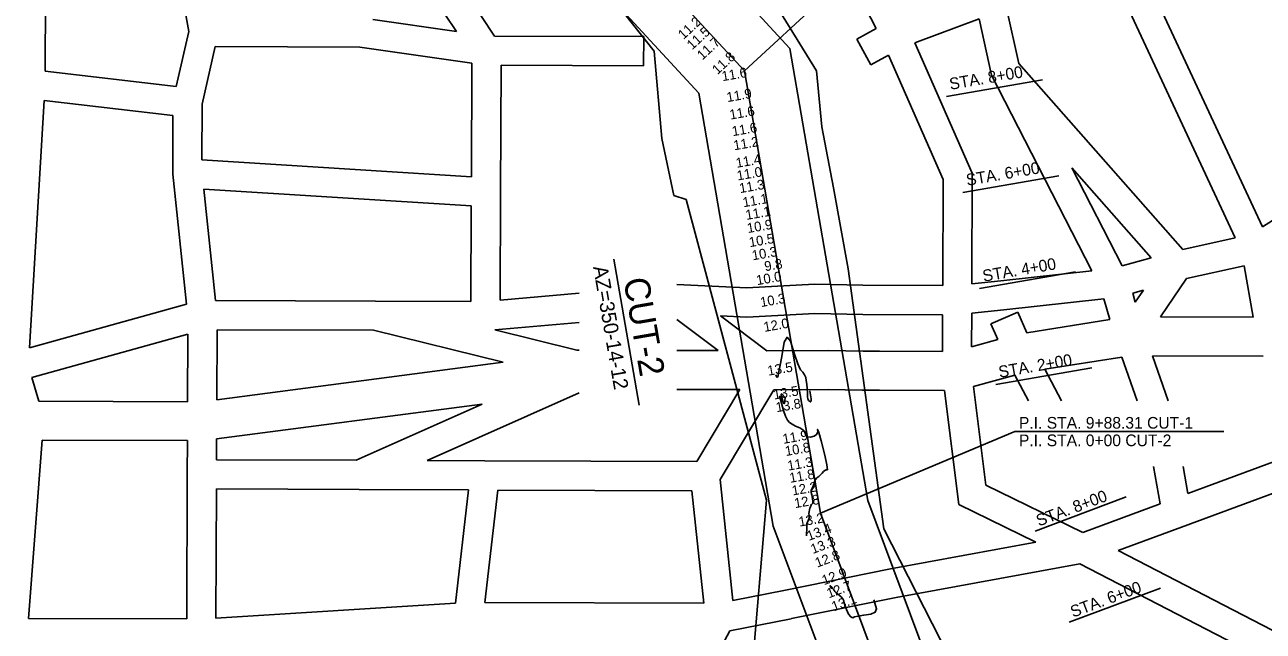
# Model space of a CAD drawing. Extents: x 503330 to 511530, y 1310349 to 1316149.
# Drawn here: x 506410 to 508954, y 1311832 to 1313078 of the extents above; entities that cross this region are included whole.
import ezdxf

# ---------------------------------------------------------------- set-up
doc = ezdxf.new("R2010")
doc.units = 0
for name, color, linetype in [('Level 1', 7, 'Continuous'), ('Level 23', 7, 'Continuous'), ('Level 32', 7, 'Continuous'), ('Level 49', 7, 'Continuous'), ('Level 5', 7, 'Continuous'), ('Level 50', 7, 'Continuous'), ('Level 51', 7, 'Continuous'), ('Level 56', 7, 'Continuous'), ('Level 6', 7, 'Continuous')]:
    doc.layers.add(name, color=color, linetype=linetype)

msp = doc.modelspace()

# ---------------------------------------------------------------- linework, layer by layer
at = {"layer": 'Level 1'}
for points in [[(508022.9, 1312326.1), (508025.1, 1312310.1), (508025.1, 1312305.2), (508024, 1312303.5), (508021.9, 1312305), (508020.2, 1312306.5), (508019.1, 1312308.1), (508018.5, 1312309.7), (508018, 1312314.1), (508017.5, 1312321.2), (508017.1, 1312331), (508016.4, 1312339.6), (508015.4, 1312347.1), (508014.2, 1312353.5), (508011.8, 1312359.3), (508008.3, 1312364.7), (508003.7, 1312369.6), (507998, 1312381.8), (507991.1, 1312401.4), (507983.1, 1312428.2), (507976, 1312436.4), (507969.9, 1312425.9), (507964.8, 1312396.8), (507961, 1312375.5), (507958.5, 1312362.3), (507957.3, 1312356.9), (507956.1, 1312354.2), (507955, 1312354), (507952.8, 1312358.9)], [(508015.7, 1312028.7), (508016.1, 1312046.3), (508016.7, 1312052.9), (508017.7, 1312057.2), (508019.1, 1312059.3), (508020.1, 1312061.3), (508020.7, 1312063.1), (508020.9, 1312064.8), (508021, 1312067.2), (508020.9, 1312070.4), (508020.7, 1312074.3), (508020.9, 1312078), (508021.6, 1312081.6), (508022.7, 1312085), (508023.8, 1312087.7), (508024.7, 1312089.7), (508025.4, 1312091.1), (508026.3, 1312092.5), (508027.4, 1312094.1), (508028.5, 1312095.7), (508028.7, 1312099.2), (508028, 1312104.8), (508026.4, 1312112.4), (508025.4, 1312117.7), (508025.1, 1312120.8), (508025.4, 1312121.6), (508026.1, 1312123.2), (508027.3, 1312125.6), (508028.9, 1312128.9), (508030.3, 1312132.4), (508031.3, 1312136.1), (508032.1, 1312140.2), (508034, 1312143.9), (508036.9, 1312147.4), (508041, 1312150.5), (508044.7, 1312153.7), (508047.9, 1312157), (508050.8, 1312160.4), (508053.5, 1312162.8), (508056.1, 1312164), (508058.7, 1312164.2), (508057.8, 1312174.1), (508053.5, 1312193.8), (508045.8, 1312223.2), (508040.8, 1312240.9), (508038.4, 1312246.8), (508038.7, 1312241.1), (508036.3, 1312236.5), (508031.4, 1312233.1), (508023.8, 1312230.8), (508018.1, 1312231.4), (508014.3, 1312234.8), (508012.4, 1312241.1), (508008.3, 1312246.3), (508002, 1312250.5), (507993.5, 1312253.8), (507986.4, 1312257.4), (507980.8, 1312261.5), (507976.6, 1312266), (507972.5, 1312274), (507968.4, 1312285.6), (507960.2, 1312316)], [(508067.1, 1311919.2), (508064.4, 1311925.5), (508064.6, 1311926.2), (508066.2, 1311924.4), (508069.4, 1311920.3), (508071.7, 1311917.2), (508073.2, 1311915.2), (508073.8, 1311914.3), (508076.2, 1311912.1), (508080.4, 1311908.5), (508086.3, 1311903.5), (508090.3, 1311899), (508092.5, 1311894.7), (508092.8, 1311890.9), (508094.5, 1311885.1), (508097.6, 1311877.3), (508102.2, 1311867.6), (508106.6, 1311861.8), (508110.6, 1311859.8), (508114.5, 1311861.7), (508122, 1311863.6), (508133.2, 1311865.5), (508148, 1311867.4), (508156.9, 1311871.7), (508159.8, 1311878.5), (508153.7, 1311896.9)]]:
    msp.add_lwpolyline(points, dxfattribs=at)
msp.add_lwpolyline([(507971.7, 1312312.8), (507971.8, 1312310.2), (507971.5, 1312307.9), (507971, 1312304.5), (507970.3, 1312300), (507969, 1312300.2), (507967.1, 1312304.9), (507964.6, 1312314.3), (507964, 1312319.3), (507965.3, 1312320)], close=True, dxfattribs=at)
at = {"layer": 'Level 23'}
for p, q in [((508468, 1312445.6), (508639, 1312472.4)), ((508743, 1312478.1), (508933.3, 1312477.4)), ((508354.9, 1312416.9), (508408.5, 1312431.8)), ((507548.6, 1312409.9), (507544.4, 1312409.9)), ((507834.2, 1312408.8), (507749.4, 1312409.1)), ((507934.2, 1312408.4), (508060.9, 1312409.1)), ((508060.9, 1312409.1), (508131.8, 1312407.7)), ((508131.8, 1312407.7), (508166, 1312407.6)), ((508166, 1312407.6), (508294.9, 1312407.1)), ((508505.1, 1312370.4), (508663.5, 1312395.3)), ((508726, 1312398.2), (508953.7, 1312397.4)), ((507393, 1312385.3), (506804.7, 1312308)), ((508358.9, 1312335), (508443.5, 1312358.4)), ((507878.6, 1312328.7), (507749.4, 1312329.1)), ((507948.4, 1312328.5), (508060.3, 1312329.1)), ((508060.3, 1312329.1), (508130.2, 1312327.7)), ((508130.2, 1312327.7), (508165.7, 1312327.6)), ((508165.7, 1312327.6), (508299.4, 1312327.1)), ((506744.7, 1312303.9), (506439, 1312305)), ((507349.5, 1312298.9), (506804.4, 1312227.3)), ((506744.4, 1312223.9), (506446.3, 1312225))]:
    msp.add_line(p, q, dxfattribs=at)
at = {"layer": 'Level 32'}
for p, q in [((506453.3, 1313286.6), (506452.1, 1312982.5)), ((508158.5, 1313070.4), (508054.2, 1313277.7)), ((506715.5, 1313245.6), (506747, 1313064.3)), ((508693, 1313218.9), (508951.9, 1312662.9)), ((508635.8, 1313199.5), (508896.2, 1312640.4)), ((507244.2, 1313143.7), (507296.7, 1313064.3)), ((507318.2, 1313140.6), (507374.8, 1313054.9)), ((508426.8, 1313112.2), (508451.6, 1312998.7)), ((507296.7, 1313064.3), (507125.3, 1313089.1)), ((508238.4, 1313041.2), (508370.2, 1313090.1)), ((508370.2, 1313090.1), (508395.4, 1312974.4)), ((506747, 1313064.3), (506721.4, 1312951.2)), ((507681.6, 1313053.8), (507374.8, 1313054.9)), ((507681.3, 1312993.8), (507681.6, 1313053.8)), ((508118.8, 1313048.3), (508158.5, 1313070.4)), ((506801.5, 1313033.5), (506774.7, 1312914.9)), ((507098.2, 1313032.3), (506801.5, 1313033.5)), ((507328.5, 1312999), (507098.2, 1313032.3)), ((508118.8, 1313048.3), (508148.1, 1312995.9)), ((508148.1, 1312995.9), (508184, 1313015.9)), ((506721.4, 1312951.2), (506452.1, 1312982.5)), ((507328.5, 1312999), (507327.6, 1312766.1)), ((507388.5, 1312994.9), (507387.5, 1312734.1)), ((507681.3, 1312993.8), (507388.5, 1312994.9)), ((508788.4, 1312616.5), (508451.6, 1312998.7)), ((508395.4, 1312974.4), (508601.7, 1312572.7)), ((506450.1, 1312922.4), (506419.9, 1312414.4)), ((506714.6, 1312891.6), (506450.1, 1312922.4)), ((506774.7, 1312914.9), (506774.3, 1312801)), ((506714.6, 1312891.6), (506714.2, 1312771.3)), ((507327.6, 1312766.1), (506774.3, 1312801)), ((508560.4, 1312784.4), (508663.8, 1312583)), ((508723.4, 1312599.5), (508560.4, 1312784.4)), ((508951.9, 1312662.9), (509129.9, 1312776.5)), ((506714.2, 1312771.3), (506742.8, 1312504)), ((506777.8, 1312740.7), (506802.3, 1312511.8)), ((507327.4, 1312706), (506777.8, 1312740.7)), ((507387.5, 1312734.1), (507386.6, 1312512.5)), ((507327.4, 1312706), (507326.6, 1312509.8)), ((508788.4, 1312616.5), (508896.2, 1312640.4)), ((508663.8, 1312583), (508723.4, 1312599.5)), ((508414.7, 1312552.4), (508601.7, 1312572.7)), ((508795.8, 1312556.7), (508914.9, 1312583.1)), ((508914.9, 1312583.1), (508933.3, 1312477.4)), ((507893.2, 1312537.9), (507749.4, 1312544.4)), ((508031.9, 1312545), (507893.2, 1312537.9)), ((508131.7, 1312543.1), (508031.9, 1312545)), ((508131.7, 1312543.1), (508295.4, 1312542.5)), ((508355.4, 1312545.9), (508414.7, 1312552.4)), ((508743, 1312478.1), (508795.8, 1312556.7)), ((507548.6, 1312527.1), (507386.6, 1312512.5)), ((508685.6, 1312526.8), (508707.5, 1312532.8)), ((508685.6, 1312526.8), (508691, 1312508.3)), ((508691, 1312508.3), (508707.5, 1312532.8)), ((506742.8, 1312504), (506419.9, 1312414.4)), ((507130.6, 1312510.5), (506802.3, 1312511.8)), ((507326.6, 1312509.8), (507130.6, 1312510.5)), ((508355.2, 1312485.5), (508421.3, 1312492.8)), ((508421.2, 1312492.8), (508626.5, 1312515)), ((508626.5, 1312515), (508639, 1312472.4)), ((507548.6, 1312466.9), (507375.7, 1312451.3)), ((507749.4, 1312473), (507834.2, 1312408.8)), ((507893.3, 1312477.8), (507839.2, 1312480.3)), ((507839.2, 1312480.3), (507934.2, 1312408.4)), ((508032.9, 1312484.9), (507893.3, 1312477.8)), ((508131.4, 1312483.1), (508032.9, 1312484.9)), ((508131.4, 1312483.1), (508295.2, 1312482.5)), ((508295.2, 1312482.5), (508294.9, 1312407.1)), ((508355.2, 1312485.5), (508354.9, 1312416.9)), ((508449.5, 1312487.8), (508394.5, 1312463.6)), ((508449.5, 1312487.8), (508468, 1312445.6)), ((506745.2, 1312442.4), (506424.8, 1312353.5)), ((506745.2, 1312442.4), (506744.7, 1312303.9)), ((506805.2, 1312451.8), (506804.7, 1312308)), ((507126.8, 1312450.6), (506805.2, 1312451.8)), ((507393, 1312385.3), (507126.8, 1312450.6)), ((507544.4, 1312409.9), (507375.7, 1312451.3)), ((508394.5, 1312463.6), (508408.5, 1312431.8)), ((508663.5, 1312395.3), (508695, 1312305.6)), ((508726, 1312398.2), (508758.6, 1312305.6)), ((506424.8, 1312353.5), (506439, 1312305)), ((507236.8, 1312182.9), (507548.6, 1312322)), ((507878.6, 1312328.7), (507790.3, 1312180.9)), ((507948.4, 1312328.5), (507838.2, 1312144)), ((508299.4, 1312327.1), (508328.3, 1312092.5)), ((508358.9, 1312335), (508383.8, 1312132.2)), ((507090.7, 1312183.5), (507349.5, 1312298.9)), ((506446.3, 1312225), (506417.8, 1311858.8)), ((506744.4, 1312223.9), (506744.1, 1312154.8)), ((506804.4, 1312227.3), (506804.2, 1312184.6)), ((508799, 1312115.1), (509028, 1312200.1)), ((507090.7, 1312183.5), (506804.2, 1312184.6)), ((507355.4, 1312182.5), (507236.8, 1312182.9)), ((507790.3, 1312180.9), (507355.4, 1312182.5)), ((508728.4, 1312171.1), (508741.8, 1312093.9)), ((508789.3, 1312171.1), (508799, 1312115.1)), ((506744.1, 1312154.8), (506743, 1311857.6)), ((507838.2, 1312144), (507864.8, 1311895.6)), ((508786.1, 1312046.3), (509049.9, 1312144.2)), ((506804, 1312124.6), (506803, 1311859.4)), ((507096.9, 1312123.5), (506804, 1312124.6)), ((507321.7, 1312122.6), (507096.9, 1312123.5)), ((507321.7, 1312122.6), (507295, 1311890.1)), ((507382, 1312122.4), (507355.5, 1311891.6)), ((507780.3, 1312120.9), (507382, 1312122.4)), ((507780.3, 1312120.9), (507805.1, 1311890)), ((508383.8, 1312132.2), (508583.3, 1312035.1)), ((508328.3, 1312092.5), (508486.5, 1312015.5)), ((508583.3, 1312035.1), (508741.8, 1312093.9)), ((508655.8, 1311998), (508786.1, 1312046.3)), ((508486.5, 1312015.5), (508188.3, 1311960.7)), ((508655.8, 1311998), (509231.9, 1311700.4)), ((508188.3, 1311960.7), (507972.8, 1311917.1)), ((508577, 1311971.1), (508199.6, 1311901.8)), ((508577, 1311971.1), (509264.6, 1311616)), ((507972.9, 1311917.1), (507864.8, 1311895.6)), ((507295, 1311890.1), (506803, 1311859.4)), ((507805.1, 1311890), (507355.5, 1311891.6)), ((508199.6, 1311901.8), (507984.7, 1311858.3)), ((506743, 1311857.6), (506417.8, 1311858.8)), ((507984.6, 1311858.2), (507858.2, 1311833.2)), ((507858.2, 1311833.2), (507766.9, 1311663.4))]:
    msp.add_line(p, q, dxfattribs=at)
for points in [[(508238.4, 1313041.2), (508356.2, 1312773.1), (508355.4, 1312545.9)], [(508184, 1313015.9), (508296.2, 1312760.6), (508295.4, 1312542.5)], [(508505.1, 1312370.4), (508539.3, 1312305.6)], [(508443.5, 1312358.4), (508471.4, 1312305.6)]]:
    msp.add_lwpolyline(points, dxfattribs=at)
at = {"layer": 'Level 5'}
for points in [[(505794, 1315948.5), (505744.2, 1315800.6), (505760.3, 1315617.2), (505843.1, 1315416.9), (505891.3, 1314808.3), (506024, 1314599.6), (506647.4, 1314056), (507642.5, 1313099.9), (507702.7, 1313024.1), (507718.9, 1312844.3), (507743.6, 1312727.6), (507768.6, 1312719.2), (507933.4, 1312101.9), (507890.2, 1311593.7)], [(508324.1, 1311750.7), (508174.9, 1312042.9), (508101.5, 1312576.5), (508071.4, 1312743.4), (508047.3, 1312868.5), (508036.4, 1312983.7), (507933.5, 1313150.3), (507770.5, 1313344.2), (506282.9, 1314790.5), (506133.6, 1315024.3), (506134.1, 1315191), (506100.8, 1315216.1), (506088.6, 1315786), (506110.2, 1315948.5)]]:
    msp.add_lwpolyline(points, dxfattribs=at)
at = {"layer": 'Level 50'}
for p, q in [((507981.8, 1313029.4), (507536.9, 1313512)), ((507794.7, 1312937.3), (507389.8, 1313376.4)), ((508141.5, 1312100.8), (507981.8, 1313029.4)), ((507947.6, 1312048.3), (507794.7, 1312937.3)), ((508484.2, 1311183.8), (508141.5, 1312100.8)), ((508296.9, 1311113.8), (507947.6, 1312048.3))]:
    msp.add_line(p, q, dxfattribs=at)
at = {"layer": 'Level 51'}
msp.add_line((507672, 1312296.6), (507620.3, 1312596.7), dxfattribs=at)
at = {"layer": 'Level 56'}
for p, q in [((507888.2, 1312983.3), (508234.3, 1313302.4)), ((508303.1, 1312930.8), (508500.2, 1312964.7)), ((508337, 1312733.7), (508534.1, 1312767.6)), ((508371, 1312536.6), (508568.1, 1312570.5)), ((508404.9, 1312339.5), (508602, 1312373.4)), ((508044.6, 1312074.6), (508443.5, 1312242.5)), ((508443.5, 1312242.5), (508872.6, 1312242.5)), ((508485.2, 1312038.2), (508672.5, 1312108.2)), ((508555.2, 1311850.8), (508742.6, 1311920.8))]:
    msp.add_line(p, q, dxfattribs=at)
at = {"layer": 'Level 6'}
for p, q in [((507888.2, 1312983.3), (506720.3, 1314250.2)), ((508044.6, 1312074.6), (507888.2, 1312983.3)), ((508390.6, 1311148.8), (508044.6, 1312074.6))]:
    msp.add_line(p, q, dxfattribs=at)

# ---------------------------------------------------------------- texts
at = {"layer": 'Level 49'}
for s, rotation, p in [('11.2 ', 42.6723, (507763, 1313046.7)), ('11.5 ', 42.6723, (507781, 1313025.7)), ('11.7 ', 42.6723, (507802, 1313004.7)), ('11.8 ', 42.6723, (507833, 1312974.7)), ('11.6 ', 9.7633, (507843.4, 1312962.2)), ('11.9 ', 9.7633, (507853.4, 1312919.2)), ('11.6 ', 9.7633, (507859.4, 1312883.2)), ('11.6 ', 9.7633, (507864.4, 1312849.2)), ('11.2 ', 9.7633, (507867.4, 1312820.2)), ('11.4 ', 9.7633, (507872.4, 1312784.2)), ('11.0 ', 9.7633, (507874.4, 1312758.2)), ('11.3 ', 9.7633, (507879.4, 1312732.2)), ('11.1 ', 9.7633, (507886.4, 1312703.2)), ('11.1 ', 9.7633, (507892.4, 1312677.2)), ('10.9 ', 9.7633, (507895.4, 1312650.2)), ('10.5 ', 9.7633, (507899.4, 1312621.2)), ('10.3 ', 9.7633, (507905.4, 1312594.2)), ('9.8', 9.7633, (507931, 1312571.8)), ('10.0 ', 9.7633, (507914.4, 1312543.2)), ('10.3 ', 9.7633, (507922.4, 1312498.2)), ('12.0 ', 9.7633, (507929.4, 1312447.2)), ('13.5 ', 9.7633, (507937.4, 1312357.2)), ('13.5 ', 9.7633, (507949.4, 1312308.2)), ('13.8 ', 9.7633, (507954.4, 1312282.2)), ('11.9 ', 9.7633, (507968.4, 1312217.2)), ('10.8 ', 9.7633, (507973.4, 1312192.2)), ('11.3 ', 9.7633, (507978.4, 1312162.2)), ('11.8 ', 9.7633, (507982.4, 1312137.2)), ('12.2 ', 9.7633, (507987.4, 1312111.2)), ('12.8 ', 9.7633, (507992.4, 1312085.2)), ('13.2 ', 9.7633, (508001.4, 1312047.2)), ('13.4 ', 20.491, (508020.7, 1312017.9)), ('13.3 ', 20.491, (508028.7, 1311990.9)), ('12.8 ', 20.491, (508037.7, 1311962.9)), ('12.9 ', 20.491, (508051.7, 1311926.9)), ('12.7 ', 20.491, (508061.7, 1311899.9)), ('13.1 ', 20.491, (508071.7, 1311872.9))]:
    msp.add_text(s, height=20, rotation=rotation, dxfattribs=at).set_placement(p)
at = {"layer": 'Level 51'}
for s, height, p in [('AZ=350-14-12', 30, (507577.4, 1312580.6)), ('CUT-2', 52, (507639.7, 1312554.8))]:
    msp.add_text(s, height=height, rotation=279.7633, dxfattribs=at).set_placement(p)
at = {"layer": 'Level 56'}
for s, rotation, p in [('STA. 8+00', 9.7633, (508311.3, 1312944.4)), ('STA. 6+00', 9.7633, (508345.6, 1312747.3)), ('STA. 4+00', 9.7633, (508379.5, 1312550.2)), ('STA. 2+00', 9.7633, (508412.3, 1312352.9)), ('STA. 8+00', 20.4909, (508492.8, 1312047.4)), ('STA. 6+00', 20.4909, (508563.1, 1311860.2))]:
    msp.add_text(s, height=24, rotation=rotation, dxfattribs=at).set_placement(p)
for s, p in [('P.I. STA. 9+88.31 CUT-1', (508452, 1312248.5)), ('P.I. STA. 0+00 CUT-2', (508452, 1312212.5))]:
    msp.add_text(s, height=24, dxfattribs=at).set_placement(p)

doc.saveas('drawing.dxf')
